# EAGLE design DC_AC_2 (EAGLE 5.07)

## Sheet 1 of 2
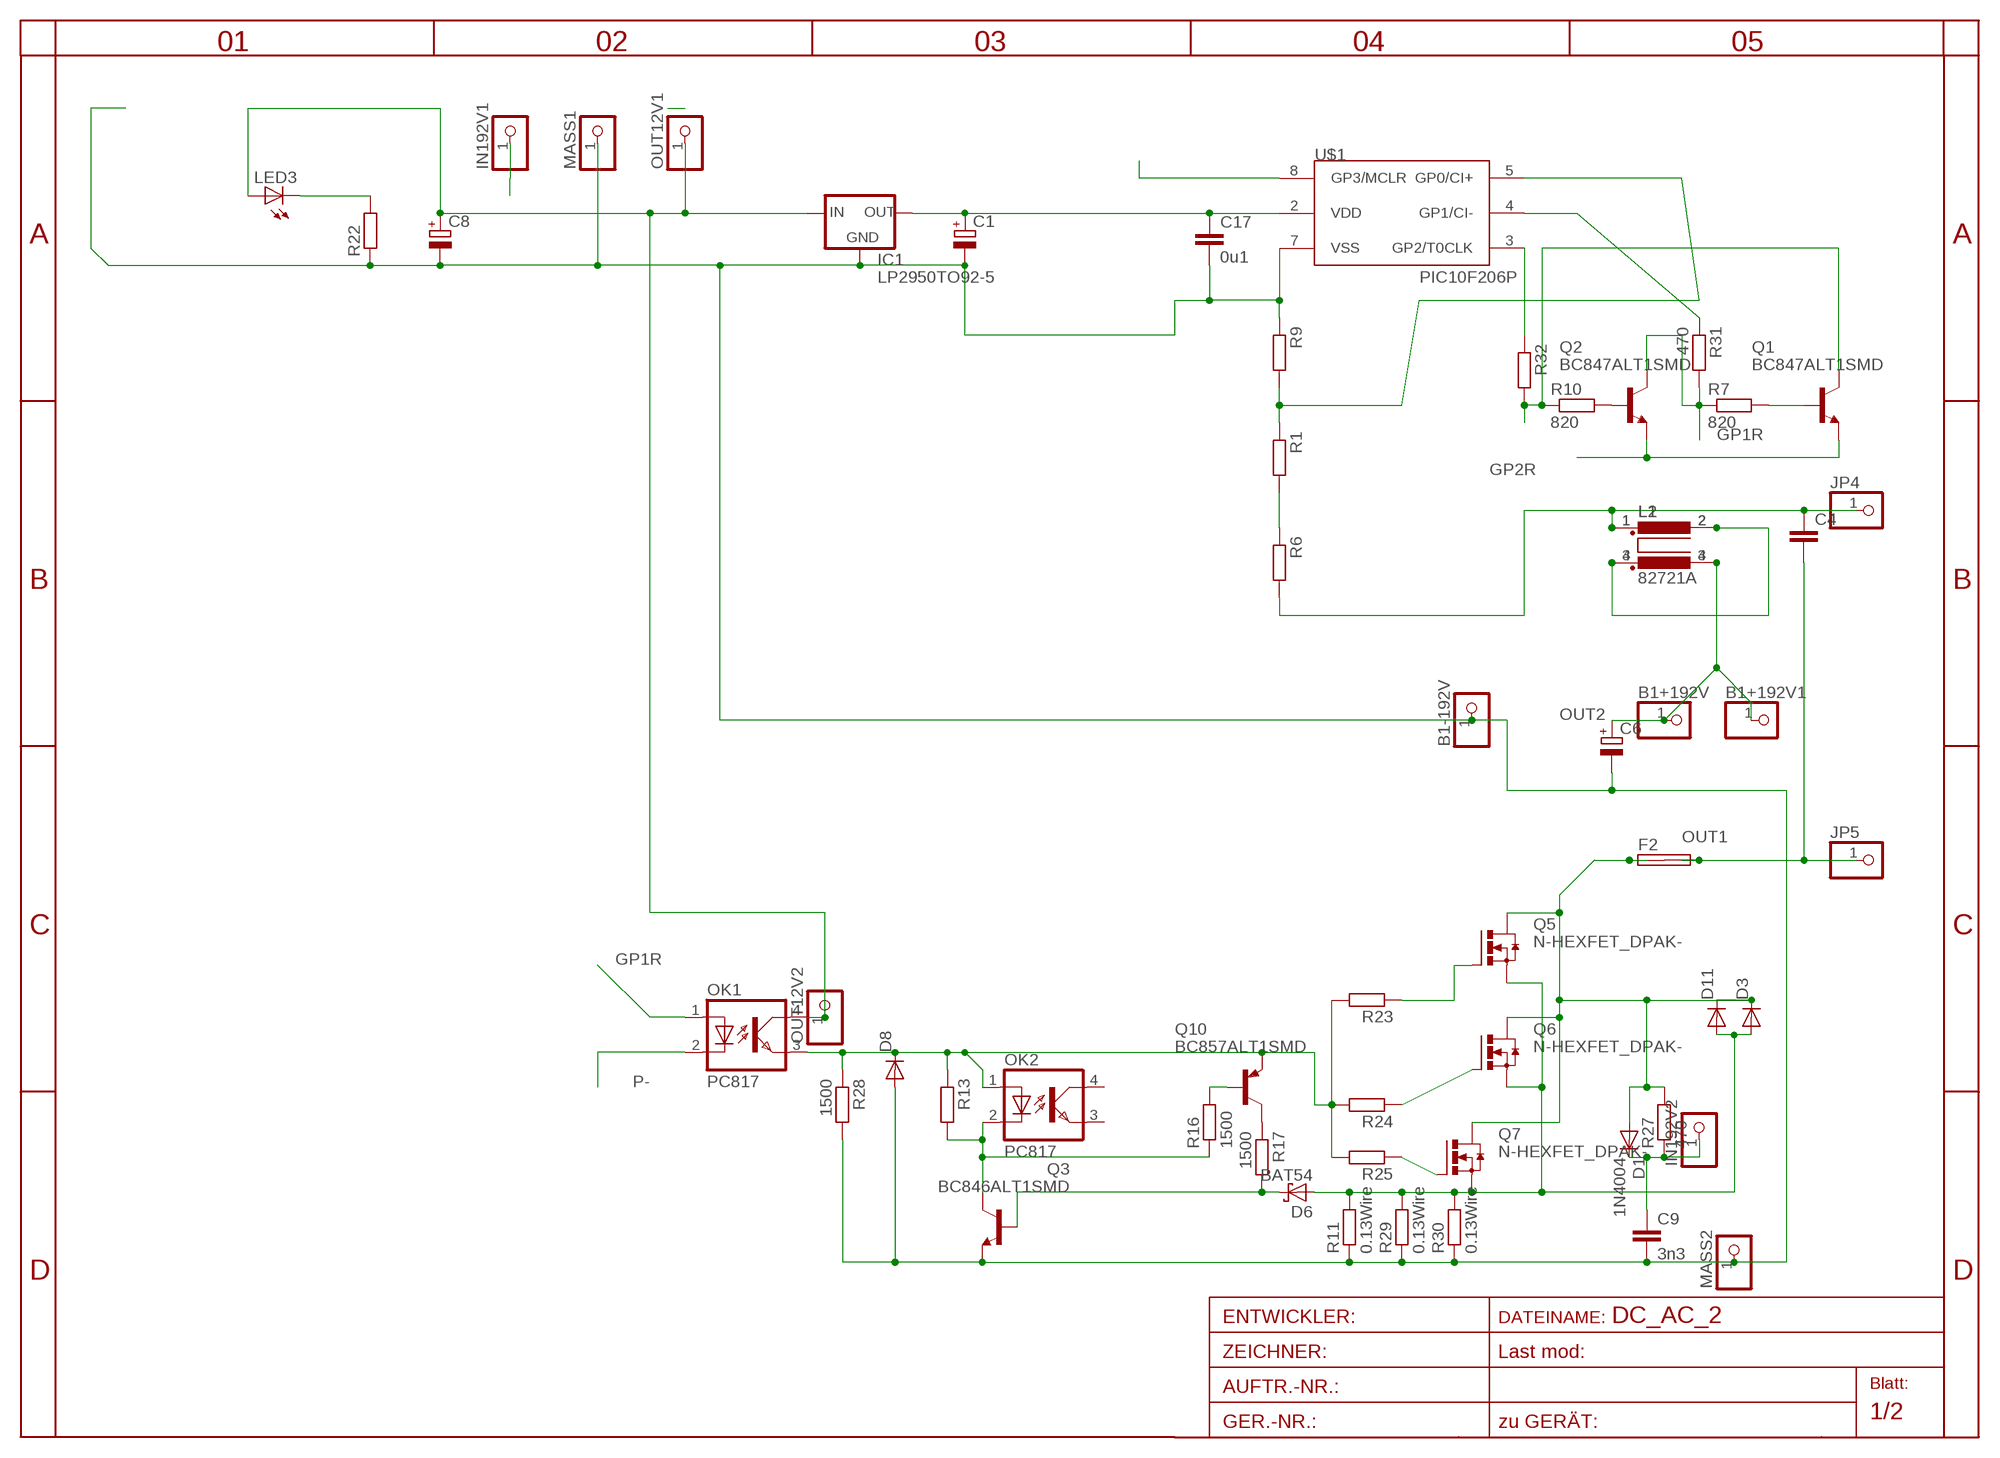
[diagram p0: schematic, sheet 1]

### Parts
B1+192V  PINHD-1X12MM3  [1X2MM3]
B1+192V1  PINHD-1X12MM3  [1X2MM3]
B1-192V  PINHD-1X12MM3  [1X2MM3]
C1  CPOL-EUE5-6  [E5-6]
C4  C-EU225-108X268  [C225-108X268]
C6  CPOL-EUE10-20  [EB20D]
C8  CPOL-EUE5-5  [E5-5]
C9  3n3  C-EU050-025X075  [C050-025X075]
C17  0u1  C-EUC1206  [C1206]
D1  1N4004  [DO41-10]
D3  DIODE-SMC  [SMC]
D6  BAT54  [SOT23]
D8  DIODE-MINIMELF  [MINIMELF]
D11  DIODE-SMC  [SMC]
F2  SHK20L7MM5  [7MM5]
IC1  LP2950TO92-5  [T092-5]
IN192V1  PINHD-1X11MM6  [1X1MM8]
IN192V2  PINHD-1X11MM6  [1X1MM8]
JP4  PINHD-1X14.5MM  [1X4MM5]
JP5  PINHD-1X14.5MM  [1X4MM5]
L1  R1405VB2  [B2]
L2  82721A  [82721A]
LED3  LEDCHIPLED_1206  [CHIPLED_1206]
MASS1  PINHD-1X11MM6  [1X1MM8]
MASS2  PINHD-1X11MM6  [1X1MM8]
OK1  PC817  [DIL04]
OK2  PC817  [DIL04]
OUT12V1  PINHD-1X11MM6  [1X1MM8]
OUT12V2  PINHD-1X11MM6  [1X1MM8]
Q1  BC847ALT1SMD  [SOT23]
Q2  BC847ALT1SMD  [SOT23]
Q3  BC846ALT1SMD  [SOT23]
Q5  N-HEXFET_DPAK-  [TO252]
Q6  N-HEXFET_DPAK-  [TO252]
Q7  N-HEXFET_DPAK-  [TO252]
Q10  BC857ALT1SMD  [SOT23-BEC]
R1  R-EU_0204/7  [0204/7]
R6  R-EU_R1206  [R1206]
R7  820  R-EU_R1206  [R1206]
R9  R-EU_R0805  [R0805]
R10  820  R-EU_R1206  [R1206]
R11  0.13Wire  R-EU_0204/5  [0204/5]
R13  R-EU_R1206  [R1206]
R16  1500  R-EU_R0805  [R0805]
R17  1500  R-EU_R0805  [R0805]
R22  R-EU_0207/10  [0207/10]
R23  R-EU_0207/15  [0207/15]
R24  R-EU_0204/2V  [0204V]
R25  R-EU_0207/12  [0207/12]
R27  470  R-EU_0207/10  [0207/10]
R28  1500  R-EU_R1206  [R1206]
R29  0.13Wire  R-EU_0204/5  [0204/5]
R30  0.13Wire  R-EU_0204/5  [0204/5]
R31  470  R-EU_R1206  [R1206]
R32  R-EU_R1206  [R1206]
U$1  PIC10F206P  [DIL8]

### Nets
AC1: C4.1 JP4.1 L1.1 L2.1 R6.2 ; also sheet 2
BATT+: C8.+ IC1.3(IN) LED3.A OK1.4(COL) OUT12V1.1 OUT12V2.1
D1: D1.A D3.C D11.C F2.1A F2.1B Q5.3(D) Q6.3(D) Q7.3(D) R27.2
GP1R: OK1.1(A) Q2.3(C) R7.1 R31.2
GP2R: Q1.3(C) R10.1 R32.2 ; also sheet 2
GP3: U$1.8(GP3/MCLR)
INN: L1.2 L1.3 L2.2 L2.4
N$1: R1.1 R9.2 U$1.5(GP0/CI+)
N$3: R1.2 R6.1
N$4: Q2.1(B) R10.2
N$7: Q1.1(B) R7.2
N$11: D6.3(C) Q3.1(B) R17.2
N$12: OK2.2(C) Q3.3(C) R13.2 R16.1
N$15: LED3.C R22.2
N$16: Q10.B R16.2
N$17: Q10.C R17.1
N$20: C9.1 D1.C IN192V2.1 R27.1
N$25: Q7.1(G) R25.1
N$26: Q6.1(G) R24.1
N$27: Q5.1(G) R23.1
N$39: R31.1 U$1.4(GP1/CI-)
N$43: R32.1 U$1.3(GP2/T0CLK)
OUT1: C4.2 F2.2A F2.2B JP5.1 ; also sheet 2
OUT2: B1+192V1.1 B1+192V.1 C6.+ IN192V1.1 L1.4 L2.3 ; also sheet 2
P-: B1-192V.1 C1.- C6.- C8.- C9.2 C17.2 D8.A IC1.2(GND) MASS1.1 MASS2.1 OK1.2(C) Q1.2(E) Q2.2(E) Q3.2(E) R9.1 R11.1 R22.1 R28.2 R29.1 R30.1 U$1.7(VSS) ; also sheet 2
PP1: D8.C OK1.3(EMIT) OK2.1(A) Q10.E R13.1 R23.2 R24.2 R25.2 R28.1
SRC1: D3.A D6.1(A) D11.A Q5.2(S) Q6.2(S) Q7.2(S) R11.2 R29.2 R30.2
VDD: C1.+ C17.1 IC1.1(OUT) U$1.2(VDD)
Unconnected: OK2.3(EMIT) OK2.4(COL)

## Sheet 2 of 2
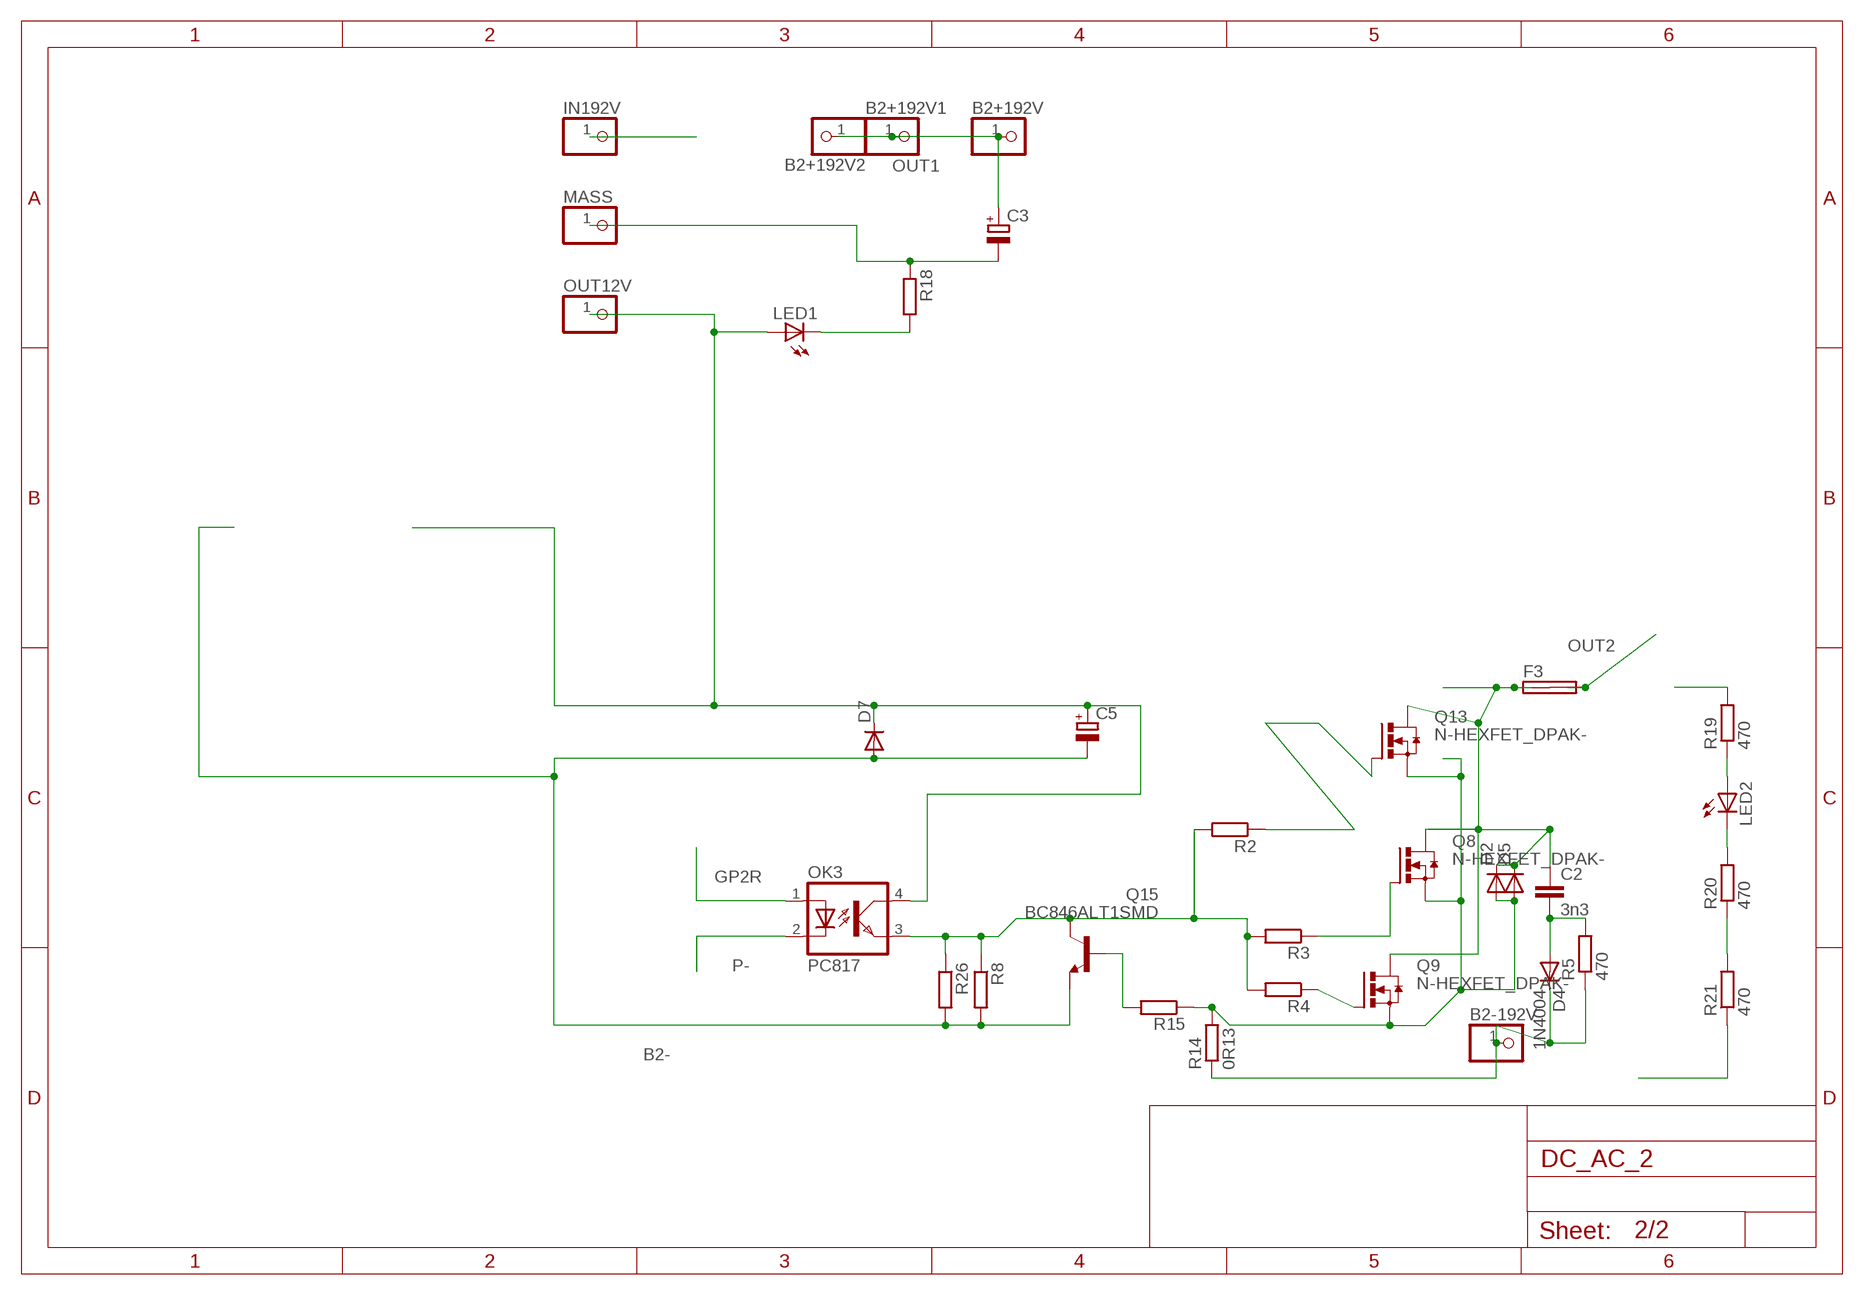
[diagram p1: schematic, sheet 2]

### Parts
B2+192V  PINHD-1X12MM3  [1X2MM3]
B2+192V1  PINHD-1X12MM3  [1X2MM3]
B2+192V2  PINHD-1X12MM3  [1X2MM3]
B2-192V  PINHD-1X12MM3  [1X2MM3]
C2  3n3  C-EU050-025X075  [C050-025X075]
C3  CPOL-EUE10-20  [EB20D]
C5  CPOL-EUE5-6  [E5-6]
D2  DIODE-SMC  [SMC]
D4  1N4004  [DO41-10]
D5  DIODE-SMC  [SMC]
D7  DIODE-MINIMELF  [MINIMELF]
F3  SHK20L7MM5  [7MM5]
IN192V  PINHD-1X11MM6  [1X1MM8]
LED1  LEDCHIPLED_1206  [CHIPLED_1206]
LED2  LED3MM  [LED3MM]
MASS  PINHD-1X11MM6  [1X1MM8]
OK3  PC817  [DIL04]
OUT12V  PINHD-1X11MM6  [1X1MM8]
Q8  N-HEXFET_DPAK-  [TO252]
Q9  N-HEXFET_DPAK-  [TO252]
Q13  N-HEXFET_DPAK-  [TO252]
Q15  BC846ALT1SMD  [SOT23]
R2  R-EU_0207/15  [0207/15]
R3  R-EU_0207/15  [0207/15]
R4  R-EU_0207/15  [0207/15]
R5  470  R-EU_0207/10  [0207/10]
R8  R-EU_R1206  [R1206]
R14  0R13  R-EU_0204/5  [0204/5]
R15  R-EU_0207/15  [0207/15]
R18  R-EU_R1206  [R1206]
R19  470  R-EU_0207/10  [0207/10]
R20  470  R-EU_0204/2V  [0204V]
R21  470  R-EU_0204/5  [0204/5]
R26  R-EU_R1206  [R1206]

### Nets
AC1: R19.2 ; also sheet 1
B2-: B2-192V.1 C3.- C5.- D4.C D7.A MASS.1 Q15.2(E) R5.1 R8.2 R14.1 R18.1 R26.2
BATT+1: C5.+ D7.C LED1.A OK3.4(COL) OUT12V.1
D2: C2.1 D2.C D5.C F3.1A F3.1B Q8.3(D) Q9.3(D) Q13.3(D)
GP2R: OK3.1(A) ; also sheet 1
N$2: Q9.1(G) R4.1
N$5: LED1.C R18.2
N$6: LED2.A R19.1
N$8: Q15.1(B) R15.2
N$9: LED2.K(C) R20.2
N$10: Q8.1(G) R3.1
N$13: R20.1 R21.2
N$18: Q13.1(G) R2.1
N$19: C2.2 D4.A R5.2
OUT1: B2+192V1.1 B2+192V2.1 B2+192V.1 C3.+ IN192V.1 R21.1 ; also sheet 1
OUT2: F3.2A F3.2B ; also sheet 1
P-: OK3.2(C) ; also sheet 1
PP2: OK3.3(EMIT) Q15.3(C) R2.2 R3.2 R4.2 R8.1 R26.1
SRC2: D2.A D5.A Q8.2(S) Q9.2(S) Q13.2(S) R14.2 R15.1

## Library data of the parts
B1+192V B1+192V1 B1-192V B2+192V B2+192V1 B2+192V2 B2-192V IN192V IN192V1 IN192V2 JP4 JP5 MASS MASS1 MASS2 OUT12V OUT12V1 OUT12V2 = pinhead:PINHD-1X1: PIN HEADER
C1 C5 C8 = rcl-2:CPOL-EU: POLARIZED CAPACITOR, European symbol
C2 C9 C17 = rcl-2:C-EU: CAPACITOR, European symbol
C3 C6 = rcl:CPOL-EU: POLARIZED CAPACITOR, European symbol
C4 = rcl:C-EU: CAPACITOR, European symbol
D1 D4 = diode:1N4004: DIODE
D2 D3 D5 D7 D8 D11 = diode:DIODE-: DIODE
D6 = diode:BAT54: Schottky Diodes
F2 F3 = fuse:SHK20L: FUSE HOLDER 5 x 20 mm, SH contact, SHH1 Schukat, E1073 Buerklin
IC1 = v-reg:LP2950?*: Source: http://cache.national.com/ds/LP/LP2950.pdf
L1 = inductor-nkl:R1405V: Übertrager (verlustarm) bis typ. 400kHz Power transformer (low loss) up to typ. 400kHz
L2 = inductors:82721A: FILTER
LED1-LED3 = led:LED: LED
OK1-OK3 = optocoupler:PC817: SHARP OPTO COUPLER
Q1 Q2 = transistor-npn:BC847*: NPN Transistor
Q3 Q15 = transistor-npn:BC846*: NPN Transistor
Q5-Q9 Q13 = transistor-power:N-HEXFET_?-*: HEXFET® Power MOSFET
Q10 = transistor-pnp:BC857*: PNP Transistror
R1-R11 R13-R32 = rcl-2:R-EU_: RESISTOR, European symbol
U$1 = microchip-5:PIC10F2*: uPC nW 0,25/0,5k Program Flash memory Comparator

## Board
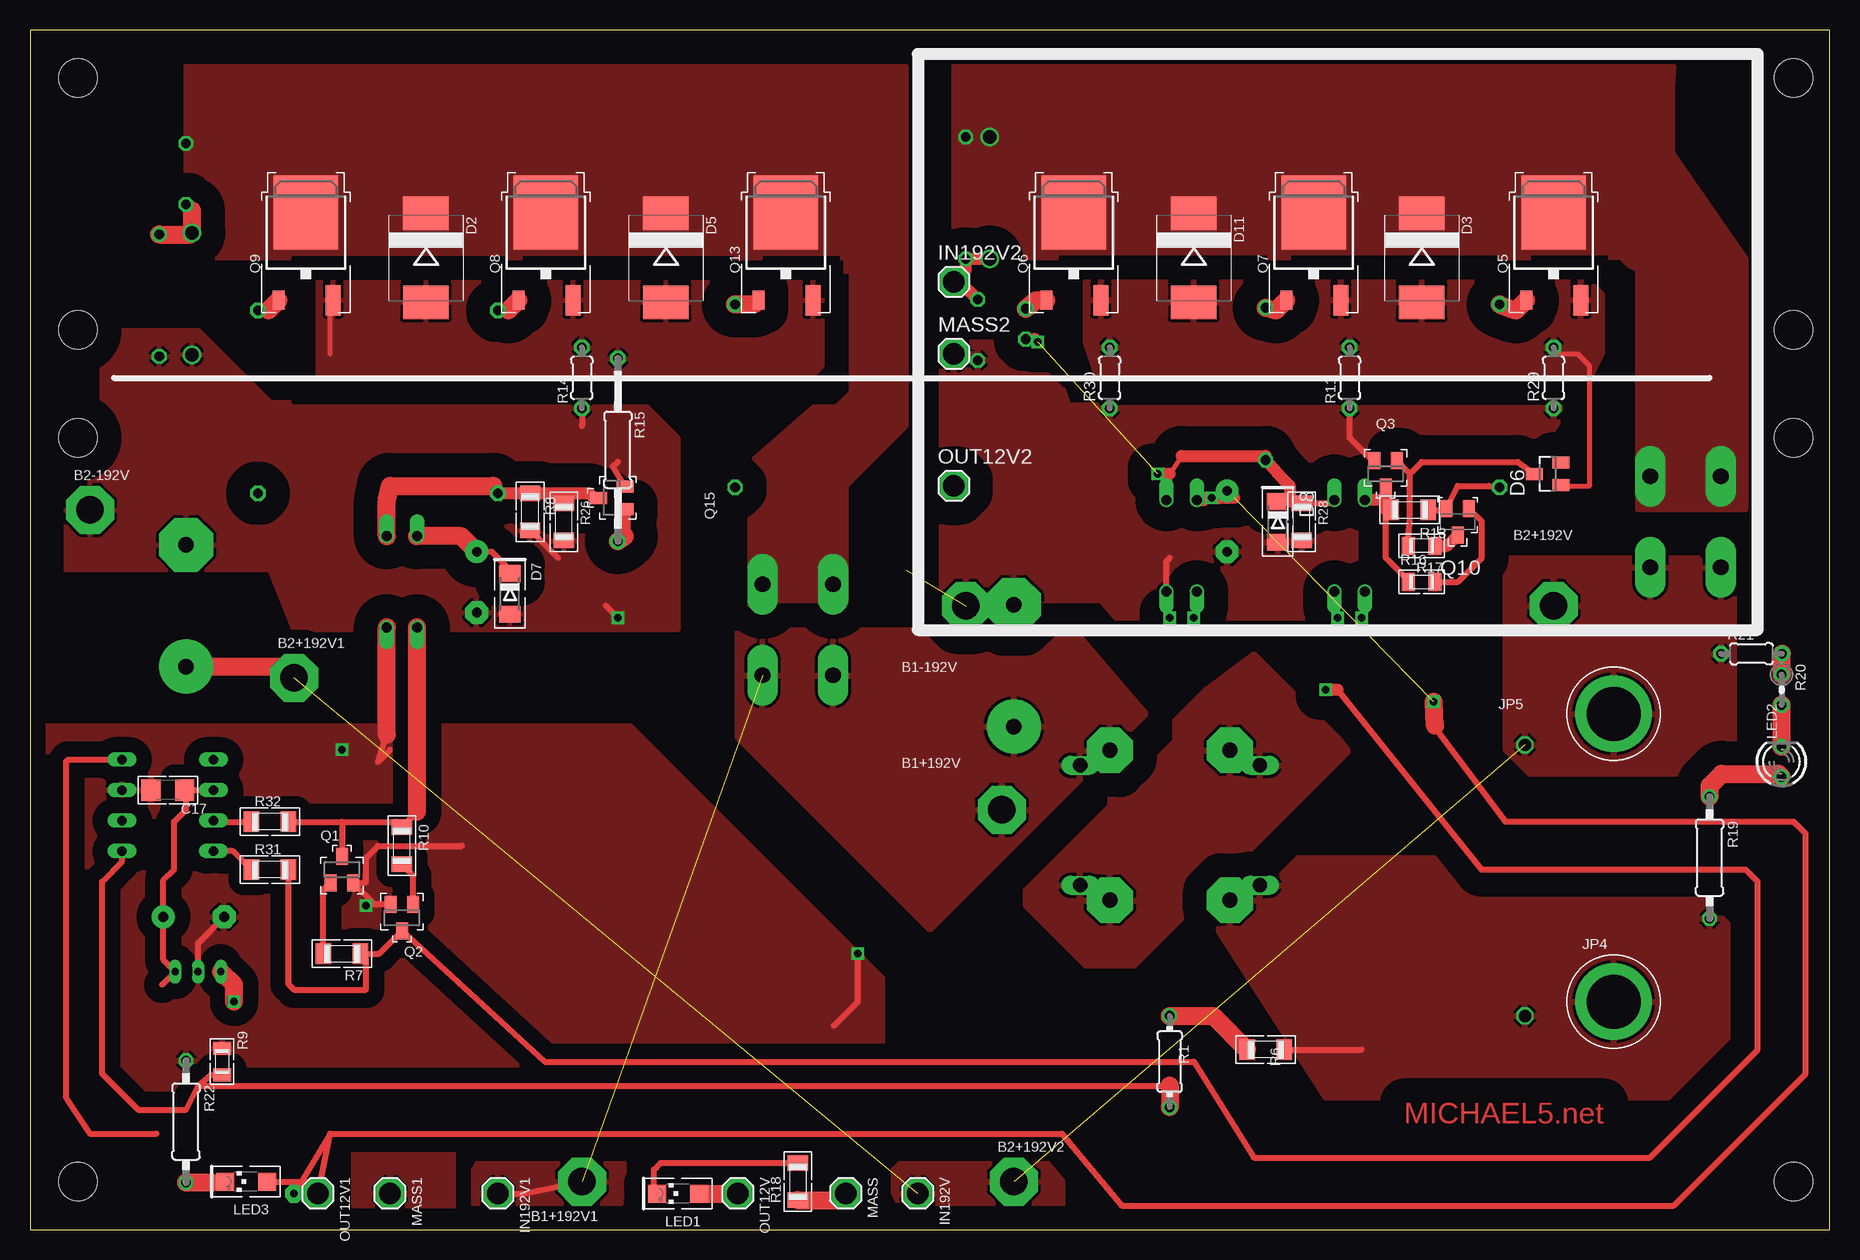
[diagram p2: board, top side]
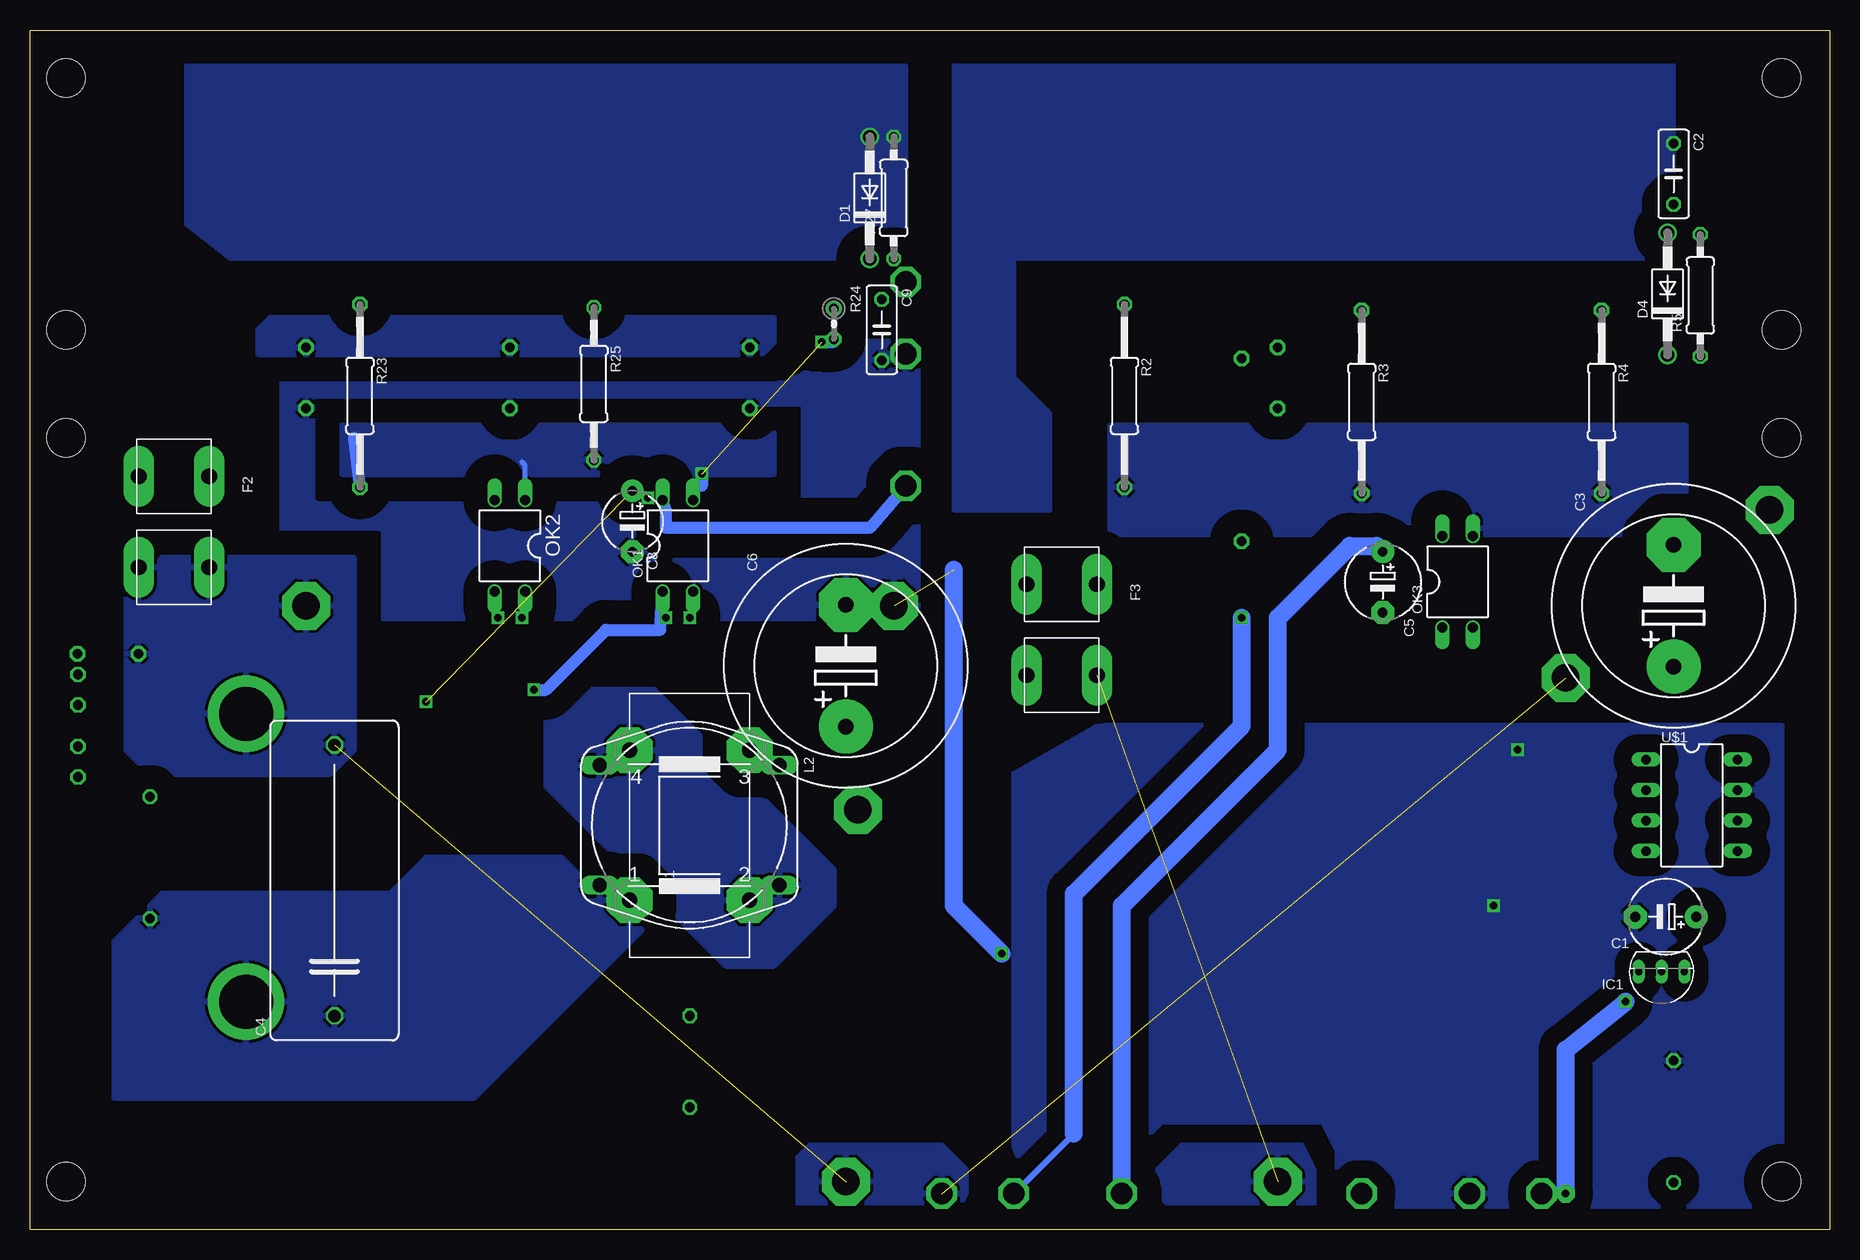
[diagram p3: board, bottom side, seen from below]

Size 150 x 100 mm. Coordinates in mm from the lower left corner, seen from the top.
Outline: 0,0 150,0 150,100 0,100 0,0
Copper layers (1*16): Top 0.035mm / dielectric 1.5mm / Bottom 0.035mm
Design rules "default *": minimum track width 12mil, minimum drill 24mil, track to track 8mil, track to pad 8mil, pad to pad 8mil, via to via 8mil, smd to smd 8mil, copper to edge 40mil, drill to drill 8mil, minimum pad ring 8mil, minimum via ring 8mil, stop-mask expansion 4mil, vias tented up to drill 0mil, thermal gap 10mil
Holes 3.2 mm at 4,96 4,4 4,75 4,66 147,96 147,4 147,75 147,66

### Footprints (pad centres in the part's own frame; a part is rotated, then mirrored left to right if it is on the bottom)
1X2MM3 = drill 2.3 pad 4 octagon: 1 0,0
E5-6 = drill 0.813 pad 1.905 round: + -2.54,0 | drill 0.813 pad 1.905 octagon: - 2.54,0
C050-025X075 = drill 0.813 octagon: 1 -2.54,0; 2 2.54,0
EB20D = drill 1.3 pad 4.5 round: + -5.08,0 | drill 1.3 pad 4.5 octagon: - 5.08,0
C225-108X268 = drill 1.016 octagon: 1 -11.303,0; 2 11.303,0
E5-5 = drill 0.813 pad 1.905 round: + -2.54,0 | drill 0.813 pad 1.905 octagon: - 2.54,0
C1206 = smd 1.6 x 1.8: 1 -1.4,0; 2 1.4,0
DO41-10 = drill 1.118 round: A 5.08,0; C -5.08,0
SMC = smd 2.8 x 3.8: A 3.7,0; C -3.7,0
SOT23 = smd 1 x 1.4: 1 -0.95,-1.1; 2 0.95,-1.1; 3 0,1.1
MINIMELF = smd 1.4 x 1.8: A 1.7,0; C -1.7,0
7MM5 = drill 1.3 pad 2.54 long: 1A -3.8,2.94; 1B -3.8,-2.94; 2A 3.8,2.94; 2B 3.8,-2.94
T092-5 = drill 0.6 pad 0.813 long: 1 -1.905,0; 2 0,0; 3 1.905,0
1X1MM8 = drill 1.8 pad 2.54 octagon: 1 0,0
1X4MM5 = drill 4.5 pad 6.35 round: 1 0,0
B2 = drill 1.27 pad 3.81 octagon: 1 -6.25,5; 2 -6.25,-5; 3 6.25,5; 4 6.25,-5
82721A = drill 1.194 long: 1 7.493,5.004; 2 -7.493,5.004; 3 -7.493,-5.004; 4 7.493,-5.004
CHIPLED_1206 = smd 1.5 x 1.5: A 0,-1.75; C 0,1.75
LED3MM = drill 0.8 pad 1.27 octagon: A -1.27,0; K 1.27,0
DIL04 = drill 0.813 offset: 1 -1.27,-3.81; 2 1.27,-3.81; 3 1.27,3.81; 4 -1.27,3.81
TO252 = smd 1 x 1.6: 1 -2.28,-3.53 | smd 1.27 x 2.54: 2 2.28,-3.53 | smd 5.4 x 6.2: 3 0,3.77
SOT23-BEC = smd 1 x 1.4: B -0.95,-1.1; C 0,1.1; E 0.95,-1.1
0204/7 = drill 0.813 octagon: 1 -3.81,0; 2 3.81,0
0207/15 = drill 0.8 pad 1.27 octagon: 1 -7.62,0; 2 7.62,0
0207/10 = drill 0.813 octagon: 1 -5.08,0; 2 5.08,0
R1206 = smd 1.3 x 1.7: 1 -1.55,0; 2 1.55,0
R0805 = smd 1.1 x 1.5: 1 -1.1,0; 2 1.1,0
0204/5 = drill 0.8 pad 1.27 octagon: 1 -2.54,0; 2 2.54,0
0204V = drill 0.8 pad 1.27 octagon: 1 -1.27,0; 2 1.27,0
0207/12 = drill 0.813 octagon: 1 -6.35,0; 2 6.35,0
DIL8 = drill 0.8 long: 1 -3.81,-3.81; 2 -1.27,-3.81; 3 1.27,-3.81; 4 3.81,-3.81; 5 3.81,3.81; 6 1.27,3.81; 7 -1.27,3.81; 8 -3.81,3.81

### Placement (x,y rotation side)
B1+192V  81,35 0 top
B1+192V1  46,4 180 top
B1-192V  78,52 0 top
B2+192V  127,52 0 top
B2+192V1  22,46 0 top
B2+192V2  82,4 0 top
B2-192V  5,60 0 top
C1  13.65,26.07 180 bottom
C2  13,88 270 bottom
C3  13,52 90 bottom
C4  124.62,29.1 90 bottom
C5  37.24,53.97 270 bottom
C6  82,47 90 bottom
C8  99.8,59.05 270 bottom
C9  79,75 270 bottom
C17  11.49,36.63 180 top
D1  80,86 90 bottom
D2  33,81 270 top
D3  116,81 270 top
D4  13.5,78 90 bottom
D5  53,81 270 top
D6  126.5,63 90 top
D7  40,53 270 top
D8  104,59 270 top
D11  97,81 270 top
F2  138,59 270 bottom
F3  64,50 270 bottom
IC1  14,21.5 180 bottom
IN192V  74,3 270 top
IN192V1  39,3 270 top
IN192V2  77,79 0 top
JP4  132,19 0 top
JP5  132,43 0 top
L1  95.03,33.7 90 bottom
L2  95.03,33.7 180 bottom
LED1  54,3 90 top
LED2  146,39 90 top
LED3  18,4 90 top
MASS  68,3 270 top
MASS1  30,3 270 top
MASS2  77,73 0 top
OK1  96,57 0 bottom
OK2  110,57 180 bottom
OK3  31,54 0 bottom
OUT12V  59,3 270 top
OUT12V1  24,3 270 top
OUT12V2  77,62 0 top
Q1  26,30 0 top
Q2  31,26 180 top
Q3  113,63 180 top
Q5  127,81 0 top
Q6  87,81 0 top
Q7  107,81 0 top
Q8  43,81 0 top
Q9  23,81 0 top
Q10  119,59 180 top
Q13  63,81 0 top
Q15  48.5,61 90 top
R1  95,14 90 top
R2  58.77,69.5 270 bottom
R3  39,69 270 bottom
R4  19,69 270 bottom
R5  10.77,77.87 90 bottom
R6  103,15 0 top
R7  26,23 180 top
R8  41.69,59.84 270 top
R9  16,14 270 top
R10  31,32 270 top
R11  110,71 90 top
R13  115,60 180 top
R14  46,71 90 top
R15  49,65 270 top
R16  116,54 0 top
R17  116,57 180 top
R18  64,4 90 top
R19  140,31 270 top
R20  146,45 270 top
R21  143.5,48 0 top
R22  13,9 270 top
R23  122.5,69.5 270 bottom
R24  83,75.5 270 bottom
R25  103,70.5 270 bottom
R26  44.5,59 270 top
R27  78,86 90 bottom
R28  106,59 270 top
R29  127,71 90 top
R30  90,71 90 top
R31  20,30 0 top
R32  20,34 0 top
U$1  11.49,35.36 270 bottom

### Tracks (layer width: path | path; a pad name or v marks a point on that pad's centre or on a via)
AC1
  Top 0.5: R6.2 111,15
  pour Top (isolate 2, rank 3): 104,31 117,31 120,28 139,28 143,24 143,11 108,11 99,25
  pour Bottom (isolate 2, rank 3): 104,31 117,31 120,28 139,28 143,24 143,11 113,11 99,25
B2-  (via drill 0.6)
  Top 0.5: Q15.2 48.6,63.6 49,64 | R8.2 42.69,57.31 44,56 | R14.1 46,67 | v49,51 48,52
  Top 1.5: R18.1 67.45,2.45 MASS.1
  Bottom 0.5: MASS.1 63,8
  Bottom 1.5: 63,8 63,28 49,42 v49,51
  pour Top (isolate 2, rank 2): 6,75 14,75 20,69 43,69 44,70 50,70 54,66 54,50 22,50 20,55 3,55 3,60 6,64
BATT+  (via drill 0.6, 0.6 pad 1.5)  (1 unrouted)
  Top 0.5: 25,8 OUT12V1.1 24,4 LED3.A | 25,8 86,8 91,2 137,2 148,13 148,33 147,34 123,34 117.48,41.36 117.12,42 | 25,8 v22,3 | C8.+ 99.8,60.81
  Top 1: v98.5,61 100.38,61 C8.+ 99.21,61 98,61 97.81,60.81 OK1.4
  Top 1.5: v17,19 17,20.41 IC1.3 | 117.12,42 v117,44
  Bottom 1: OUT12V2.1 80,58.5 97,58.5 97,60 OK1.4
  Bottom 1.5: v22,3 22,15 v17,19
BATT+1
  Top 0.5: C5.+ 38.49,56.51 40,55 D7.C
  Top 1.5: OK3.4 35.94,57.81 C5.+ | LED1.A OUT12V.1
  Bottom 0.5: 37.73,57 C5.+
  Bottom 1.5: OUT12V.1 59,27 46,40 46,51 40,57 37.73,57
D1
  pour Top (isolate 2, rank 2, no thermals): 77,97 137,97 136.89,95.25 136.89,89.82 143,81 143,60 134,60 134,80 132,81 77,81
  pour Bottom (isolate 2, rank 2, no thermals): 77,97 137,97 137,83.82 133.35,81 77,81
D2
  pour Top (isolate 2, rank 2, no thermals): 13,97 73,97 73,67 68,62 68,52 60,52 60,64 68,71 68,81 13,81
  pour Bottom (isolate 2, rank 2, no thermals): 13,97 73,97 73,60 65,60 65,68 68,71 68,81 13,81
GP1R  (via drill 0.6)
  Top 0.5: R31.2 21.55,20.45 22,20 28,20 28,22.55 R7.1 29.1,23 Q2.3 42.9,14 97,14 102,6 135,6 144,15 144,29 143,30 121,30 109,45
  Top 1: 109,45 v108,45
  Bottom 1: v108,45 107,45 102,50 97.46,50 OK1.1
GP2R
  Top 0.5: R32.2 26,34 | 26,34 30.55,34 R10.1 32.27,34.82 | 26,34 Q1.3
  Top 1.5: 32.27,34.82 OK3.1
GP3
  Top 0.5: U$1.8 3.17,39.17 3,39 3,11 5,8 10.55,8
INN
  pour Top (isolate 2, rank 2): 98,45 102,48 110,40 92,22 88,22 83,27 83,30
  pour Bottom (isolate 2, rank 2): 98,45 107,45 107,37 92,22 88,22 83,27 83,30
N$1
  Top 0.5: U$1.5 7.68,30.68 6,29 6,13 9,10 13,10 14,12 | 14,12 95,12 | R9.2 15.1,12.9 14,12
  Top 1.5: 95,12 R1.1
N$2
  Top 0.5: R4.1 19.87,76.62
  Top 1.5: 19.87,76.62 Q9.1
N$3
  Top 1.5: R1.2 98.64,17.81 R6.1
N$4
  Top 0.5: Q2.1 31.95,29.5 R10.2
N$5
  Top 0.5: R18.2 52.55,5.55 52,5 52,3.25 LED1.C
N$6
  Top 1.5: R19.1 140,37 141,38 145.73,38 LED2.A
N$7
  Top 0.5: R7.2 24.45,28.3 Q1.1
N$8
  Top 1: 49.6,57.78 Q15.1
  Top 1.5: R15.2 49.6,57.78
N$9
  Top 1.5: LED2.K R20.2
N$10
  Top 0.5: R3.1 39.87,76.62
  Top 1.5: 39.87,76.62 Q8.1
N$11
  Top 0.5: R17.2 114.9,57.9 115,59 115,62.96 | 115,62.96 Q3.1 | 115,62.96 116,64 124,64 D6.3
N$12
  Top 0.5: R16.1 114.9,54.1 113,56 113,60
  Top 1: 113,60.81 113,60 R13.2 | 113,60.81 OK2.2 | 113,60.81 Q3.3
N$13
  Top 1.5: R21.2 146.04,46.31 R20.1
N$15
  Top 0.5: 15.17,3.92 LED3.C
  Top 1.5: R22.2 15.17,3.92
N$16
  Top 0.5: R16.2 119,54 121,56 121,59.05 Q10.B
N$17
  Top 1: R17.1 118.1,57 Q10.C
N$18
  Top 0.5: Q13.1 60.37,77.12
  Top 1.5: 60.37,77.12 R2.1
N$19
  Top 0.5: 13.37,82.95 D4.A | 13.5,84.96 C2.2
  Top 1.5: R5.2 13.37,82.95 | D4.A 13.5,84.96
N$20
  Top 1: D1.C R27.1 78,80 IN192V2.1 77.54,79 C9.1
N$21  (via drill 0.6)
  other vias: 111,51
N$22  (via drill 0.6)
  other vias: 109,51
N$23  (via drill 0.6)
  other vias: 97,51
N$24  (via drill 0.6)
  other vias: 95,51
N$25
  Top 1.5: R25.1 103.87,76.62 Q7.1
N$26
  Top 1.5: Q6.1 83.85,77.47 R24.1
N$27
  Top 1.5: R23.1 123.87,76.62 Q5.1
N$39
  Top 0.5: U$1.4 16.9,31.55 R31.1
N$43
  Top 0.5: R32.1 15.39,34 U$1.3
OUT1  (2 unrouted)
  Top 1.5: C3.+ 21.08,46.92 B2+192V1.1
  pour Top (isolate 2): 123,56 139,56 142,53 142,40 140,38 125,38 123,40
  pour Bottom (isolate 2): 123,56 139,56 142,53 142,40 140,38 125,38 123,40
  pour Top (isolate 2): 72,3 72,5 74,7 85,7 86,6 86,1 73,1
  pour Bottom (isolate 2): 72,3 72,5 74,7 85,7 86,6 86,1 73,1
OUT2  (1 unrouted)
  Top 0.5: B1+192V1.1 41,3 IN192V1.1
  pour Top (isolate 2): 59,50 87,50 93,43 75,25 59,41
  pour Top (isolate 2): 38,7 48,7 50,5 50,3 49,2 37,2 37,5
  pour Bottom (isolate 2): 44,7 54,7 56,5 56,3 55,2 43,2 43,5
P-  (via drill 0.6)  (1 unrouted)
  Top 0.5: 29.73,41.27 29,39 30,40 | Q2.2 28.75,27.1 Q1.2 27.9,28.9 28,29 28,31 29,32 36,32 | OK1.2 94.73,55.73 95,56 | v69,23 69,19 67,17 | IC1.2 14,23.88 C1.- | Q3.2 111.62,64.38 110,66 R11.1
  Top 1.5: 29.73,41.27 OK3.2
  Bottom 1.5: 73,55 73,27 v69,23
  other vias: 28,27 26,40
  pour Top (isolate 1.27, rank 3): 1,12 1,42 50,42 71,21 71,4 67,2 27,2 27,11
  pour Bottom (isolate 1.5, rank 3): 4,42 61,42 68,38 68,7 66,2 6,2 4,7
  pour Top (isolate 2, rank 3): 76,74 82,74 86,70 129,70 119,54 117,51 76,51
  pour Bottom (isolate 2, rank 3): 76,74 82,74 86,71 129,71 129,55 122,51 76,51
PP1  (via drill 0.6)  (1 unrouted)
  Top 0.406: 96,64.5 95,63 95,61.08 OK1.3 | 103,64.5 R25.2
  Top 0.5: D8.C 105,60.7 105.85,60.7 R28.1 108.47,60.55 OK2.1 | R23.2 121.62,62 119,62 Q10.E 117.95,60 R13.1
  Top 1: 96,64.5 103,64.5 | R25.2 104.35,62.65 105,62 105,60.7 | R24.2 83.77,74.23 v84,74 | 95,63 v94,63
  Bottom 0.406: OK2.1 108.73,63.73 109,64 | R25.2 103,65
  Bottom 1: R23.2 123,66 | v84,74 83,74 | v94,63 94,62
  pour Bottom (isolate 2, rank 2): 88,67 124,67 124,63 88,63
PP2
  Top 1: R26.1 44.08,60.55 44.08,61.3 44,61.38 | 38.62,62 38.62,61.76 R3.2 42,61.38 | 42,61.38 44,61.38 | 44,61.38 46.62,61.38 47,61 Q15.3 | R8.1 41.99,61.39 42,61.38
  Top 1.5: OK3.3 29.73,60.73 30,62 38.62,62
  pour Bottom (isolate 2): 12,67 60,67 60,58 12,58
SRC1
  Top 0.406: R29.2 127.54,73 129,73 130,72 130,62 127.65,62 D6.1
  pour Top (isolate 2): 88,79 130,79 131,78 131,73 130,71 89,71 88,74
  pour Bottom (isolate 2): 88,76 130,76 131,75 131,73 89,73 88,74
SRC2
  Top 0.406: Q9.2 25,77.47 25,73
  pour Top (isolate 2): 24,79 66,79 66,72 65,71 24,71
VDD
  Top 0.5: U$1.2 C17.1 13,36.52 13,35 12,34 12,30 11.11,29.11 C1.+ 11.11,22.48 IC1.1 11,20.41

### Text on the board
Top: MICHAEL5.net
